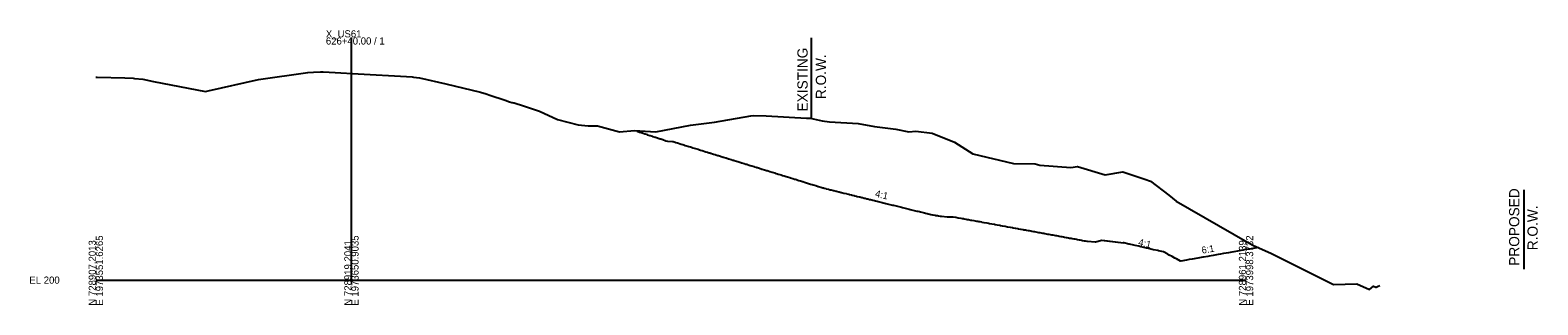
# Model space of a CAD drawing. Extents: x -26 to 630, y -39 to 9098.
# Drawn here: x -26 to 564, y 5990 to 6098 of the extents above; entities that cross this region are included whole.
import ezdxf

# ---------------------------------------------------------------- set-up
doc = ezdxf.new("R2010")
doc.units = 0
for name, color, linetype in [('CONST_DCH', 7, 'Continuous'), ('Default', 7, 'Continuous'), ('Draft_XS_Grid', 7, 'Continuous'), ('DTM_X_GROUND', 7, 'Continuous'), ('X_DTM_CONTOURS_MAJOR', 7, 'Continuous'), ('XS_CELL', 7, 'Continuous'), ('XS_P_GROUND', 7, 'Continuous'), ('XS_P_ROW', 7, 'Continuous'), ('XS_P_TX_FS_BS', 7, 'Continuous'), ('XS_X_ROW', 7, 'Continuous')]:
    doc.layers.add(name, color=color, linetype=linetype)

msp = doc.modelspace()

# ---------------------------------------------------------------- linework, layer by layer
at = {"layer": 'DTM_X_GROUND'}
msp.add_lwpolyline([(0, 6079.48), (0.48, 6079.48), (11.34, 6079.13), (14.55, 6079.03), (15.13, 6078.97), (18.43, 6078.62), (22.61, 6077.79), (42.87, 6073.81), (43.97, 6074.06), (63.65, 6078.58), (82.98, 6081.25), (85.15, 6081.43), (87.86, 6081.52), (88.93, 6081.56), (93.68, 6081.3), (102.7, 6080.8), (121.49, 6079.65), (123.7, 6079.51), (124.29, 6079.45), (126.69, 6079.17), (136.9, 6076.79), (150.45, 6073.61), (152.77, 6072.85), (154.13, 6072.4), (160.16, 6070.4), (161.88, 6069.84), (162.81, 6069.53), (162.9, 6069.51), (163.4, 6069.42), (163.71, 6069.37), (167.36, 6068.22), (173.62, 6066.18), (180.6, 6062.83), (188.72, 6060.78), (192.68, 6060.32), (196.21, 6060.39), (204.94, 6058.05), (210.75, 6058.54), (219.1, 6058.08), (232.72, 6060.58), (242.09, 6061.8), (256.27, 6064.28), (257.43, 6064.41), (262.27, 6064.26), (278.04, 6063.38), (279.43, 6063.42), (284.23, 6062.37), (287.1, 6062), (298.23, 6061.32), (304.63, 6060.09), (313.03, 6059.14), (318.1, 6057.98), (320.86, 6058.28), (327.17, 6057.45), (335.91, 6054.02), (343.06, 6049.44), (359.05, 6045.65), (367.45, 6045.46), (369.32, 6045.01), (381.44, 6044.06), (384.1, 6044.43), (394.95, 6041.22), (401.85, 6042.32), (410.37, 6039.52), (412.64, 6038.75), (419.79, 6033.21), (422.68, 6030.89), (450.6, 6014.91), (452.69, 6013.66), (460, 6010.45), (484.28, 5998.23), (493.38, 5998.6), (498.29, 5996.38), (499.85, 5997.58), (500.82, 5997.23), (500.88, 5997.26), (500.89, 5997.26), (500.9, 5997.27), (501.67, 5997.56), (502.41, 5997.85)], dxfattribs=at)
at = {"layer": 'XS_CELL'}
for p, q in [((100, 6000), (100, 6095)), ((0, 6000), (100, 6000)), ((100, 6000), (450, 6000))]:
    msp.add_line(p, q, dxfattribs=at)
at = {"layer": 'XS_P_GROUND'}
for points in [[(211.75, 6058.29), (211.77, 6058.28), (211.79, 6058.27), (212.77, 6057.95), (212.82, 6057.93), (213.78, 6057.62), (213.85, 6057.6), (214.78, 6057.29), (214.87, 6057.26), (215.78, 6056.96), (215.9, 6056.92), (216.79, 6056.63), (216.93, 6056.58), (217.79, 6056.3), (217.95, 6056.25), (218.8, 6055.97), (218.97, 6055.91), (219.8, 6055.64), (220, 6055.57), (220.8, 6055.31), (221.02, 6055.24), (221.81, 6054.98), (222.05, 6054.9), (222.81, 6054.65), (223.03, 6054.57), (223.64, 6054.37), (223.74, 6054.36), (225.63, 6054.28), (225.93, 6054.19), (226.63, 6053.98), (226.95, 6053.88), (227.63, 6053.67), (227.97, 6053.56), (228.63, 6053.36), (228.98, 6053.25), (229.63, 6053.05), (230, 6052.93), (230.63, 6052.74), (231.03, 6052.62), (231.63, 6052.43), (232.06, 6052.3), (232.63, 6052.12), (233.09, 6051.98), (233.63, 6051.81), (234.11, 6051.66), (234.63, 6051.5), (235.14, 6051.35), (235.63, 6051.2), (236.16, 6051.03), (236.63, 6050.89), (237.19, 6050.71), (237.63, 6050.58), (238.22, 6050.39), (238.63, 6050.27), (239.25, 6050.08), (239.63, 6049.96), (240.02, 6049.84), (240.24, 6049.77), (240.5, 6049.69), (240.63, 6049.65), (241.32, 6049.44), (241.63, 6049.34), (242.35, 6049.12), (242.63, 6049.03), (243.38, 6048.8), (243.63, 6048.72), (244.41, 6048.48), (244.63, 6048.42), (245.45, 6048.16), (245.63, 6048.11), (246.5, 6047.84), (246.63, 6047.8), (247.54, 6047.52), (247.63, 6047.49), (248.6, 6047.19), (248.63, 6047.18), (249.27, 6046.98), (249.57, 6046.89), (249.59, 6046.88), (249.63, 6046.87), (249.71, 6046.85), (250.63, 6046.56), (251.18, 6046.39), (251.63, 6046.25), (252.41, 6046.01), (252.63, 6045.94), (252.77, 6045.9), (253.64, 6045.63), (254.36, 6045.41), (254.64, 6045.33), (255.12, 6045.18), (255.64, 6045.02), (255.94, 6044.92), (256.64, 6044.71), (257.52, 6044.43), (257.64, 6044.4), (258.32, 6044.19), (258.64, 6044.09), (258.88, 6044.02), (259.64, 6043.78), (260.6, 6043.48), (260.64, 6043.47), (260.69, 6043.46), (261.64, 6043.16), (262.34, 6042.95), (262.64, 6042.85), (263.06, 6042.72), (263.64, 6042.55), (264.64, 6042.24), (264.64, 6042.24), (264.65, 6042.23), (265.64, 6041.93), (266.21, 6041.75), (266.64, 6041.62), (267, 6041.51), (267.64, 6041.31), (268.12, 6041.16), (268.64, 6041), (269.36, 6040.78), (269.64, 6040.69), (270.15, 6040.54), (270.64, 6040.38), (271.51, 6040.11), (271.64, 6040.07), (271.72, 6040.05), (272.64, 6039.77), (273.29, 6039.57), (273.64, 6039.46), (274.07, 6039.32), (274.64, 6039.15), (275.07, 6039.02), (275.64, 6038.84), (276.42, 6038.6), (276.64, 6038.53), (277.21, 6038.36), (277.64, 6038.22), (278.42, 6037.98), (278.64, 6037.91), (278.77, 6037.87), (279.64, 6037.6), (280.3, 6037.4), (280.64, 6037.29), (281.12, 6037.15), (281.65, 6036.98), (282.59, 6036.69), (282.65, 6036.68), (282.68, 6036.67), (283.65, 6036.37), (284.37, 6036.14), (284.65, 6036.06), (285.02, 6035.97), (285.65, 6035.81), (285.8, 6035.77), (286.65, 6035.56), (287.36, 6035.39), (287.65, 6035.32), (287.66, 6035.31), (288.65, 6035.07), (288.69, 6035.06), (289.65, 6034.82), (289.73, 6034.8), (290.65, 6034.58), (290.76, 6034.55), (291.65, 6034.33), (291.79, 6034.3), (292.65, 6034.08), (292.81, 6034.04), (293.65, 6033.84), (293.84, 6033.79), (294.65, 6033.59), (294.86, 6033.54), (295.65, 6033.34), (295.89, 6033.28), (296.65, 6033.09), (296.91, 6033.03), (297.65, 6032.85), (297.93, 6032.78), (298.65, 6032.6), (298.95, 6032.53), (299.65, 6032.35), (299.97, 6032.28), (300.65, 6032.11), (300.99, 6032.02), (301.65, 6031.86), (302, 6031.77), (302.65, 6031.61), (303.02, 6031.52), (303.65, 6031.37), (304.03, 6031.27), (304.65, 6031.12), (305.05, 6031.02), (305.65, 6030.87), (306.06, 6030.77), (306.65, 6030.63), (307.08, 6030.52), (307.65, 6030.38), (308.09, 6030.27), (308.65, 6030.13), (309.1, 6030.02), (309.66, 6029.88), (310.11, 6029.77), (310.66, 6029.64), (311.13, 6029.52), (311.66, 6029.39), (312.14, 6029.27), (312.66, 6029.14), (313.15, 6029.02), (313.66, 6028.9), (314.16, 6028.77), (314.66, 6028.65), (315.17, 6028.52), (315.66, 6028.4), (316.14, 6028.28), (316.66, 6028.16), (317.14, 6028.04), (317.66, 6027.91), (318.15, 6027.79), (318.66, 6027.66), (319.17, 6027.54), (319.66, 6027.42), (320.18, 6027.29), (320.66, 6027.17), (321.19, 6027.04), (321.66, 6026.92), (322.21, 6026.79), (322.66, 6026.67), (323.22, 6026.54), (323.66, 6026.43), (324.24, 6026.28), (324.66, 6026.18), (325.26, 6026.03), (325.66, 6025.93), (326.28, 6025.78), (326.66, 6025.69), (327.3, 6025.6), (327.66, 6025.51), (328.32, 6025.43), (328.66, 6025.34), (329.34, 6025.25), (329.66, 6025.17), (330.37, 6025.07), (330.66, 6024.99), (330.82, 6024.97), (330.89, 6024.96), (333.06, 6024.76), (333.11, 6024.76), (335.32, 6024.7), (335.36, 6024.7), (336.34, 6024.62), (336.42, 6024.6), (337.37, 6024.43), (337.43, 6024.42), (338.43, 6024.24), (338.44, 6024.24), (338.9, 6024.15), (339.46, 6024.05), (339.76, 6024), (340.47, 6023.87), (340.92, 6023.78), (341.48, 6023.68), (342.35, 6023.52), (342.5, 6023.5), (342.69, 6023.46), (343.51, 6023.31), (344.08, 6023.21), (344.52, 6023.13), (345.14, 6023.01), (345.53, 6022.94), (345.81, 6022.89), (346.55, 6022.76), (346.67, 6022.73), (347.37, 6022.61), (347.53, 6022.58), (347.56, 6022.57), (347.6, 6022.56), (348.57, 6022.39), (349.25, 6022.26), (349.58, 6022.2), (349.79, 6022.16), (350.6, 6022.02), (351.46, 6021.86), (351.61, 6021.83), (351.84, 6021.79), (352.62, 6021.65), (353.56, 6021.48), (353.63, 6021.46), (353.93, 6021.41), (354.65, 6021.28), (354.68, 6021.27), (355.66, 6021.09), (355.74, 6021.08), (356.67, 6020.91), (356.8, 6020.89), (357.69, 6020.72), (357.85, 6020.69), (358.7, 6020.54), (358.9, 6020.5), (359.71, 6020.35), (359.95, 6020.31), (360.72, 6020.17), (360.99, 6020.12), (361.74, 6019.99), (362.04, 6019.93), (362.75, 6019.8), (363.08, 6019.74), (363.76, 6019.62), (364.12, 6019.55), (364.77, 6019.43), (365.15, 6019.36), (365.79, 6019.25), (366.19, 6019.17), (366.8, 6019.06), (367.22, 6018.98), (367.81, 6018.88), (368.26, 6018.8), (368.82, 6018.69), (369.29, 6018.61), (369.84, 6018.51), (370.32, 6018.42), (370.85, 6018.32), (371.35, 6018.23), (371.86, 6018.14), (372.38, 6018.04), (372.88, 6017.95), (373.41, 6017.85), (373.89, 6017.77), (374.44, 6017.67), (374.9, 6017.58), (375.47, 6017.48), (375.91, 6017.4), (376.49, 6017.29), (376.93, 6017.21), (377.52, 6017.11), (377.94, 6017.03), (378.54, 6016.92), (378.95, 6016.84), (379.57, 6016.73), (379.96, 6016.66), (380.59, 6016.54), (380.98, 6016.47), (381.62, 6016.36), (381.99, 6016.29), (382.64, 6016.17), (383, 6016.1), (383.66, 6015.99), (384.01, 6015.92), (384.67, 6015.8), (385.03, 6015.73), (385.69, 6015.61), (386.04, 6015.55), (386.7, 6015.43), (387.05, 6015.37), (387.67, 6015.25), (387.99, 6015.19), (390.96, 6015.03), (391.05, 6015.04), (393.57, 6015.62), (393.65, 6015.62), (394.46, 6015.52), (394.7, 6015.49), (395.54, 6015.39), (395.75, 6015.36), (396.63, 6015.25), (396.8, 6015.23), (397.71, 6015.12), (397.85, 6015.1), (398.79, 6014.99), (398.9, 6014.97), (399.88, 6014.85), (399.96, 6014.84), (400.97, 6014.72), (401.01, 6014.72), (402, 6014.59)], [(417.68, 6011.04), (415.81, 6011.47), (415.54, 6011.53), (413.86, 6011.91), (413.32, 6012.03), (411.91, 6012.35), (411.09, 6012.53), (409.96, 6012.79), (408.87, 6013.04), (408.02, 6013.23), (406.65, 6013.54), (406.07, 6013.67), (404.42, 6014.04), (404.12, 6014.11), (402.2, 6014.55), (402.17, 6014.55), (402, 6014.59)], [(424.4, 6007.42), (422.75, 6008.31), (422.21, 6008.6), (421.08, 6009.21), (419.99, 6009.8), (419.41, 6010.11), (417.76, 6011), (417.74, 6011.01), (417.68, 6011.04)], [(454.76, 6012.75), (453.44, 6012.52), (453.34, 6012.5), (451.37, 6012.15), (451.12, 6012.11), (449.31, 6011.79), (448.9, 6011.72), (447.26, 6011.43), (446.67, 6011.33), (445.22, 6011.08), (444.45, 6010.94), (443.18, 6010.72), (442.22, 6010.55), (441.15, 6010.36), (440, 6010.16), (439.13, 6010.01), (437.78, 6009.77), (437.11, 6009.65), (435.55, 6009.38), (435.1, 6009.3), (433.33, 6008.99), (433.1, 6008.95), (431.11, 6008.6), (431.11, 6008.6), (431.1, 6008.6), (428.88, 6008.21), (427.78, 6008.01), (426.66, 6007.82), (424.45, 6007.43), (424.44, 6007.43), (424.4, 6007.42)]]:
    msp.add_lwpolyline(points, dxfattribs=at)
at = {"layer": 'XS_P_ROW'}
msp.add_line((558.73, 6035.35), (558.73, 6004.34), dxfattribs=at)
at = {"layer": 'XS_X_ROW'}
msp.add_line((280, 6063.44), (280, 6094.8), dxfattribs=at)

# ---------------------------------------------------------------- texts
at = {"layer": 'CONST_DCH'}
for p in [(424.4, 6007.42), (431.11, 6008.6)]:
    msp.add_text('X', height=0.001, dxfattribs=at).set_placement(p)
at = {"layer": 'Default'}
for height, p in [(0.12, (220.07, 6058.2)), (0.001, (417.68, 6011.04)), (0.001, (424.4, 6007.42))]:
    msp.add_text('X', height=height, dxfattribs=at).set_placement(p)
at = {"layer": 'Draft_XS_Grid'}
msp.add_text('-', height=0.0001, dxfattribs=at).set_placement((0, 6000))
at = {"layer": 'X_DTM_CONTOURS_MAJOR'}
msp.add_text('X', height=0.12, dxfattribs=at).set_placement((270.12, 6038.58))
at = {"layer": 'XS_CELL'}
for s, p in [('X_US61', (90, 6095)), ('626+40.00 / 1', (90, 6092.2)), ('EL 200', (-26, 5998.6))]:
    msp.add_text(s, height=2.8, dxfattribs=at).set_placement(p)
for s, p in [('E 1973551.6265', (2.8, 5990)), ('E 1973650.9035', (102.8, 5990)), ('E 1973998.3732', (452.8, 5990)), ('N 728907.2013', (0, 5990)), ('N 728919.2041', (100, 5990)), ('N 728961.2139', (450, 5990))]:
    msp.add_text(s, height=2.8, rotation=90, dxfattribs=at).set_placement(p)
at = {"layer": 'XS_P_ROW'}
for s, p in [('EXISTING', (278.49, 6066.02)), ('R.O.W.', (285.69, 6070.86)), ('PROPOSED', (556.92, 6005.61)), ('R.O.W.', (564.12, 6011.69))]:
    msp.add_text(s, height=4, rotation=90, dxfattribs=at).set_placement(p)
at = {"layer": 'XS_P_TX_FS_BS'}
for s, rotation, p in [('4:1', 347.06589, (304.71, 6032.64)), ('4:1', 347.23995, (407.67, 6013.62)), ('6:1', 9.95235, (432.85, 6010.31))]:
    msp.add_text(s, height=2.7, rotation=rotation, dxfattribs=at).set_placement(p)

doc.saveas('drawing.dxf')
